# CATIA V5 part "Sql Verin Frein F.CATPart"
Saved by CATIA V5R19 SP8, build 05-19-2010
Part number: Sql Verin Frein F
Publications: "Droite.1", "Point.6", "Point.1"
Bounding box of the stored display mesh (mm): x 0 to 0, y -1370 to 0, z -1500 to -1500
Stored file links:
  G:\EU_thinkMotion\CFAO_2010\MMS_groupe3\MMS_groupe3\rdalborgo\rdalborgo\Sql Verin Frein F.CATPart
  G:\EU_thinkMotion\CFAO_2010\MMS_groupe3\MMS_groupe3\rdalborgo\rdalborgo\rdalborgo.CATProduct
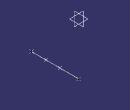
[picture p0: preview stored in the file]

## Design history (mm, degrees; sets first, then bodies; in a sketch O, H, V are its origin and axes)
Set1
  Point1 "A verin frein": linked copy from another document
  Point2 "B verin frein": linked copy from another document
Set2
  Point3: (0, -420, 0), relative to Point1
  Line1: type PtPt, FirstPoint Point2, SecondPoint Point3
  Point4: type OnCurve, Support Line1, Ratio 0.4
Body1 (main body)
